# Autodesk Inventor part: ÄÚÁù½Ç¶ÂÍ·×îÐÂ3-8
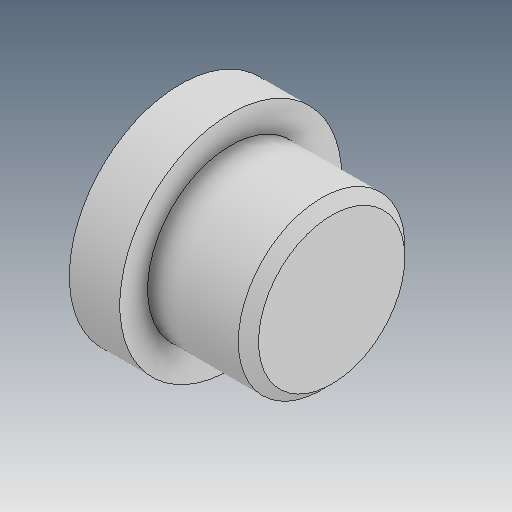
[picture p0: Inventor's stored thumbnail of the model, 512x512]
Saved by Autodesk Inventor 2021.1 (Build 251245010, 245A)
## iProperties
Created: 2019-04
Part Number: ÄÚÁù½Ç¶ÂÍ·×îÐÂ3-8
Material: Ogólny
Document SubType Name: Modeling
Designer: user
Density: 1 g/cm^3
Appearance: Domyślna
Author: user
Revision Number: ÈÎºÎ
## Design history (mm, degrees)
feature "ÊäÈë1"
node "Bryła1"
